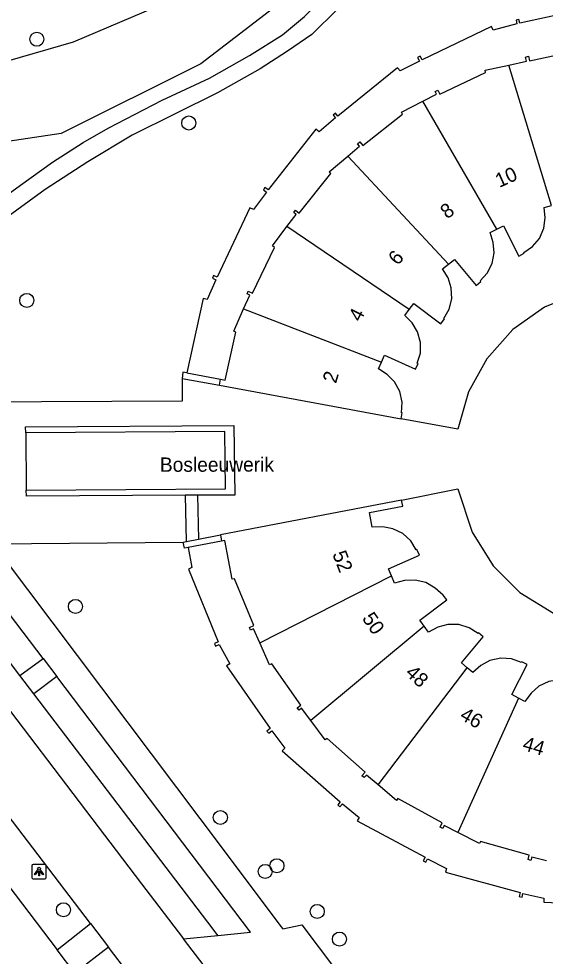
# Model space of a CAD drawing. Extents: x 156664 to 157568, y 383571 to 384421.
# Drawn here: x 157008.2 to 157044.9, y 384065.3 to 384130.7 of the extents above; entities that cross this region are included whole.
import ezdxf

# ---------------------------------------------------------------- set-up
doc = ezdxf.new("R2010")
doc.units = 0
for name, color, linetype in [('IMGEO_Boom', 7, 'Continuous'), ('IMGEO_Fietspad_gesloten', 7, 'Continuous'), ('IMGEO_Greppel_droge_sloot', 7, 'Continuous'), ('IMGEO_Groenvoorziening', 7, 'Continuous'), ('IMGEO_Lichtpunt', 7, 'Continuous'), ('IMGEO_Muur', 7, 'Continuous'), ('IMGEO_Openbare_ruimte_label', 7, 'Continuous'), ('IMGEO_Pand', 7, 'Continuous'), ('IMGEO_Pand_nummerreeks', 7, 'Continuous'), ('IMGEO_Parkeervlak_open', 7, 'Continuous'), ('IMGEO_Rijbaan_lokaal_gesloten', 7, 'Continuous'), ('IMGEO_Rijbaan_lokaal_open', 7, 'Continuous'), ('IMGEO_Voetpad_gesloten', 7, 'Continuous'), ('IMGEO_Voetpad_halfverhard', 7, 'Continuous'), ('IMGEO_Voetpad_open', 7, 'Continuous')]:
    doc.layers.add(name, color=color, linetype=linetype)

msp = doc.modelspace()

# ---------------------------------------------------------------- linework, layer by layer
at = {"layer": 'IMGEO_Boom'}
for centre in [(157009.428, 384129.265), (157020.016, 384123.422), (157008.728, 384111.051), (157012.118, 384089.707), (157022.219, 384074.989), (157026.16, 384071.625), (157025.342, 384071.225), (157011.285, 384068.552), (157028.973, 384068.439), (157030.517, 384066.51)]:
    msp.add_circle(centre, 0.489, dxfattribs=at)
at = {"layer": 'IMGEO_Fietspad_gesloten'}
for points in [[(156992.949, 384089.063), (156993.81, 384088.011), (156999.63, 384080.515), (157010.848, 384065.748)], [(157012.072, 384064.137), (157010.848, 384065.748)]]:
    msp.add_lwpolyline(points, dxfattribs=at)
at = {"layer": 'IMGEO_Greppel_droge_sloot'}
msp.add_lwpolyline([(157029.595, 384139.138), (157030.878, 384136.293), (157028.032, 384133.073), (157020.852, 384127.544), (157011.124, 384122.683), (157001.811, 384121.29), (156998.763, 384122.638), (157003.697, 384126.69), (157011.975, 384129.074), (157020.136, 384132.567), (157029.595, 384139.138)], dxfattribs=at)
at = {"layer": 'IMGEO_Groenvoorziening'}
for points in [[(157048.127, 384131.481), (157043.095, 384130.384), (157043.028, 384130.645), (157042.825, 384130.593), (157042.892, 384130.331), (157041.237, 384129.908), (157041.118, 384130.156), (157036.279, 384127.836), (157036.154, 384128.079), (157035.969, 384127.983), (157036.093, 384127.743), (157034.746, 384127.057), (157034.572, 384127.271), (157030.415, 384123.905), (157030.234, 384124.118), (157030.072, 384123.98), (157030.247, 384123.775), (157029.094, 384122.813), (157028.877, 384122.984), (157025.551, 384118.755), (157025.324, 384118.924), (157025.217, 384118.753), (157025.434, 384118.592), (157024.534, 384117.386), (157024.285, 384117.503), (157022.003, 384112.671), (157021.75, 384112.785), (157021.666, 384112.595), (157021.913, 384112.485), (157021.294, 384111.118), (157021.03, 384111.176), (157019.882, 384105.99)], [(157019.977, 384093.821), (157020.243, 384092.419), (157019.993, 384092.314), (157022.059, 384087.243), (157021.801, 384087.126), (157021.887, 384086.945), (157022.134, 384087.057), (157022.88, 384085.711), (157022.658, 384085.557), (157025.688, 384081.187), (157025.465, 384081.017), (157025.587, 384080.858), (157025.802, 384081.021), (157026.715, 384079.829), (157026.537, 384079.627), (157030.572, 384076.083), (157030.398, 384075.874), (157030.555, 384075.734), (157030.727, 384075.942), (157031.892, 384074.991), (157031.764, 384074.753), (157036.482, 384072.223), (157036.352, 384071.966), (157036.528, 384071.869), (157036.65, 384072.11), (157037.988, 384071.44), (157037.913, 384071.18), (157043.117, 384069.755), (157043.052, 384069.484), (157043.241, 384069.428), (157043.304, 384069.69), (157044.771, 384069.367), (157044.759, 384069.094), (157050.113, 384068.857)]]:
    msp.add_lwpolyline(points, dxfattribs=at)
at = {"layer": 'IMGEO_Lichtpunt'}
for p, q in [((157009.085, 384071.62), (157009.085, 384070.813)), ((157009.085, 384071.62), (157009.085, 384070.813)), ((157009.987, 384071.715), (157009.179, 384071.715)), ((157009.987, 384071.715), (157009.179, 384071.715)), ((157010.081, 384070.813), (157010.081, 384071.62)), ((157010.081, 384070.813), (157010.081, 384071.62)), ((157009.179, 384070.719), (157009.987, 384070.719)), ((157009.179, 384070.719), (157009.987, 384070.719))]:
    msp.add_line(p, q, dxfattribs=at)
for points in [[(157009.459, 384071.284), (157009.498, 384071.256), (157009.31, 384070.994), (157009.272, 384071.021), (157009.459, 384071.284)], [(157009.561, 384071.236), (157009.608, 384071.236), (157009.608, 384070.914), (157009.561, 384070.914), (157009.561, 384071.236)], [(157009.671, 384071.256), (157009.709, 384071.283), (157009.896, 384071.021), (157009.857, 384070.993), (157009.671, 384071.256)]]:
    msp.add_lwpolyline(points, dxfattribs=at)
msp.add_circle((157009.584, 384071.418), 0.0994, dxfattribs=at)
for centre, start, end in [((157009.179, 384071.62), 90, 180), ((157009.179, 384071.62), 90, 180), ((157009.987, 384071.62), 0, 90), ((157009.987, 384071.62), 0, 90), ((157009.179, 384070.813), 180, 270), ((157009.179, 384070.813), 180, 270), ((157009.987, 384070.813), 270, 0), ((157009.987, 384070.813), 270, 360)]:
    msp.add_arc(centre, 0.0946, start, end, dxfattribs=at)
at = {"layer": 'IMGEO_Muur'}
for points in [[(157019.882, 384105.99), (157019.616, 384106.039), (157019.547, 384105.61)], [(157019.882, 384105.99), (157022.239, 384105.555)], [(157019.547, 384105.61), (157022.161, 384105.134)], [(157008.652, 384101.811), (157008.649, 384102.241), (157023.17, 384102.337), (157023.227, 384097.478), (157020.634, 384097.464)], [(157008.697, 384097.827), (157022.572, 384097.905), (157022.525, 384101.903), (157008.652, 384101.811)], [(157019.801, 384097.459), (157008.7, 384097.397), (157008.697, 384097.827)], [(157020.634, 384097.464), (157019.801, 384097.459)], [(157019.622, 384094.19), (157019.862, 384094.236)], [(157019.977, 384093.821), (157019.712, 384093.771), (157019.622, 384094.19)], [(157019.862, 384094.236), (157020.693, 384094.396)], [(157022.3, 384094.267), (157019.977, 384093.821)], [(157020.693, 384094.396), (157022.222, 384094.691)]]:
    msp.add_lwpolyline(points, dxfattribs=at)
at = {"layer": 'IMGEO_Pand'}
for points in [[(157042.322, 384127.458), (157043.551, 384127.728), (157043.486, 384128.025), (157043.689, 384128.077), (157043.759, 384127.755), (157047.016, 384128.46), (157047.013, 384128.62), (157048.696, 384128.653)], [(157036.336, 384124.956), (157037.285, 384125.441), (157037.192, 384125.629), (157037.375, 384125.722), (157037.52, 384125.433), (157040.705, 384126.94), (157040.67, 384127.096), (157042.322, 384127.458)], [(157045.3, 384117.659), (157042.322, 384127.458)], [(157031.102, 384121.115), (157031.914, 384121.8), (157031.788, 384121.968), (157031.944, 384122.1), (157032.139, 384121.853), (157034.906, 384124.041), (157034.832, 384124.186), (157036.336, 384124.956)], [(157041.479, 384116.024), (157036.336, 384124.956)], [(157026.859, 384116.199), (157027.498, 384117.048), (157027.336, 384117.178), (157027.45, 384117.345), (157027.713, 384117.136), (157029.919, 384119.902), (157029.814, 384120.027), (157031.102, 384121.115)], [(157031.102, 384121.115), (157038.119, 384113.575)], [(157041.479, 384116.024), (157041.945, 384116.251), (157043.012, 384114.146), (157043.389, 384114.342), (157043.361, 384114.395), (157043.97, 384114.805), (157044.455, 384115.378), (157044.755, 384116.087), (157044.858, 384116.808), (157044.788, 384117.54), (157045.3, 384117.659)], [(157023.841, 384110.452), (157024.273, 384111.42), (157024.086, 384111.515), (157024.163, 384111.705), (157024.455, 384111.565), (157025.984, 384114.749), (157025.846, 384114.853), (157026.859, 384116.199)], [(157035.386, 384110.419), (157026.859, 384116.199)], [(157038.119, 384113.575), (157038.527, 384113.904), (157040.038, 384112.093), (157040.361, 384112.367), (157040.322, 384112.413), (157040.824, 384112.949), (157041.169, 384113.615), (157041.304, 384114.373), (157041.243, 384115.099), (157041.012, 384115.797), (157041.479, 384116.024)], [(157035.386, 384110.419), (157035.706, 384110.832), (157037.593, 384109.417), (157037.847, 384109.757), (157037.799, 384109.793), (157038.167, 384110.428), (157038.354, 384111.155), (157038.316, 384111.924), (157038.094, 384112.618), (157037.712, 384113.246), (157038.119, 384113.575)], [(157022.239, 384105.555), (157022.552, 384105.497), (157023.303, 384108.845), (157023.154, 384108.912), (157023.841, 384110.452)], [(157023.841, 384110.452), (157033.449, 384106.75)], [(157033.449, 384106.75), (157033.667, 384107.221), (157035.824, 384106.264), (157035.999, 384106.642), (157035.944, 384106.666), (157036.157, 384107.369), (157036.172, 384108.119), (157035.958, 384108.858), (157035.581, 384109.483), (157035.065, 384110.006), (157035.386, 384110.419)], [(157034.816, 384102.793), (157034.893, 384103.21), (157034.834, 384103.221), (157034.884, 384103.953), (157034.731, 384104.688), (157034.357, 384105.36), (157033.85, 384105.885), (157033.23, 384106.279), (157033.449, 384106.75)], [(157022.161, 384105.134), (157022.239, 384105.555)], [(157022.161, 384105.134), (157034.816, 384102.793)], [(157034.843, 384097.129), (157022.222, 384094.691)], [(157034.144, 384091.831), (157033.933, 384092.33), (157036.091, 384093.284), (157035.916, 384093.67), (157035.862, 384093.645), (157035.484, 384094.275), (157034.939, 384094.79), (157034.248, 384095.129), (157033.532, 384095.27), (157032.798, 384095.24), (157032.618, 384096.262), (157034.935, 384096.708), (157034.843, 384097.129)], [(157022.222, 384094.691), (157022.3, 384094.267)], [(157024.965, 384087.165), (157024.524, 384088.144), (157024.329, 384088.057), (157024.248, 384088.24), (157024.55, 384088.375), (157023.209, 384091.632), (157023.046, 384091.608), (157022.52, 384094.309), (157022.3, 384094.267)], [(157024.965, 384087.165), (157034.144, 384091.831)], [(157036.419, 384088.326), (157036.114, 384088.747), (157038.002, 384090.163), (157037.745, 384090.5), (157037.189, 384090.993), (157036.541, 384091.373), (157035.792, 384091.548), (157035.063, 384091.526), (157034.354, 384091.332), (157034.144, 384091.831)], [(157036.419, 384088.326), (157028.525, 384081.743)], [(157039.423, 384085.436), (157039.03, 384085.776), (157040.545, 384087.586), (157040.214, 384087.86), (157040.176, 384087.814), (157039.561, 384088.215), (157038.845, 384088.44), (157038.075, 384088.441), (157037.37, 384088.255), (157036.723, 384087.906), (157036.419, 384088.326)], [(157028.525, 384081.743), (157027.879, 384082.603), (157027.702, 384082.469), (157027.58, 384082.628), (157027.827, 384082.821), (157025.796, 384085.699), (157025.654, 384085.635), (157024.965, 384087.165)], [(157042.986, 384083.317), (157042.528, 384083.561), (157043.604, 384085.661), (157043.224, 384085.85), (157043.198, 384085.797), (157042.507, 384086.047), (157041.759, 384086.101), (157041.009, 384085.927), (157040.366, 384085.584), (157039.816, 384085.097), (157039.423, 384085.436)], [(157033.207, 384077.256), (157039.423, 384085.436)], [(157046.949, 384082.039), (157046.447, 384082.173), (157047.019, 384084.461), (157046.602, 384084.562), (157046.588, 384084.504), (157045.859, 384084.595), (157045.117, 384084.482), (157044.425, 384084.146), (157043.873, 384083.67), (157043.444, 384083.073), (157042.986, 384083.317)], [(157042.986, 384083.317), (157038.778, 384073.936)], [(157033.207, 384077.256), (157032.397, 384077.939), (157032.244, 384077.766), (157032.086, 384077.905), (157032.308, 384078.156), (157029.656, 384080.496), (157029.531, 384080.402), (157028.525, 384081.743)], [(157038.778, 384073.936), (157037.82, 384074.428), (157037.718, 384074.23), (157037.54, 384074.324), (157037.686, 384074.624), (157034.593, 384076.31), (157034.484, 384076.18), (157033.207, 384077.256)], [(157044.955, 384071.963), (157043.919, 384072.224), (157043.861, 384071.996), (157043.665, 384072.048), (157043.741, 384072.369), (157040.356, 384073.306), (157040.283, 384073.163), (157038.778, 384073.936)]]:
    msp.add_lwpolyline(points, dxfattribs=at)
at = {"layer": 'IMGEO_Parkeervlak_open'}
for points in [[(157008.252, 384084.883), (157004.436, 384089.91), (157002.783, 384088.679)], [(157022.05, 384066.767), (157021.725, 384067.195), (157009.23, 384083.609)]]:
    msp.add_lwpolyline(points, dxfattribs=at)
at = {"layer": 'IMGEO_Rijbaan_lokaal_gesloten'}
msp.add_lwpolyline([(157008.652, 384101.811), (157008.697, 384097.827)], dxfattribs=at)
at = {"layer": 'IMGEO_Rijbaan_lokaal_open'}
for points in [[(157013.176, 384067.588), (156995.355, 384090.962)], [(157002.783, 384088.679), (157016.726, 384070.36), (157017.934, 384068.772), (157019.642, 384066.527)], [(157013.176, 384067.588), (157014.424, 384065.95)], [(157021.082, 384064.634), (157019.642, 384066.527)], [(157067.449, 383996.186), (157062.167, 384003.14), (157022.83, 384054.925), (157020.102, 384058.503), (157014.424, 384065.95)]]:
    msp.add_lwpolyline(points, dxfattribs=at)
at = {"layer": 'IMGEO_Voetpad_gesloten'}
for points in [[(157019.862, 384094.236), (157019.801, 384097.459)], [(157020.634, 384097.464), (157020.693, 384094.396)]]:
    msp.add_lwpolyline(points, dxfattribs=at)
at = {"layer": 'IMGEO_Voetpad_halfverhard'}
for points in [[(156994.084, 384110.528), (156997.761, 384111.981), (157001.193, 384113.9), (157008.294, 384119.078), (157010.532, 384120.698), (157012.649, 384122.072), (157014.412, 384123.063), (157018.159, 384125.008), (157021.465, 384126.549), (157024.262, 384128.135), (157026.54, 384129.566), (157028.082, 384130.851), (157029.891, 384132.736), (157030.956, 384134.504), (157031.273, 384135.669), (157031.39, 384136.396), (157031.332, 384137.044), (157031.044, 384137.849), (157029.957, 384139.919)], [(157032.41, 384137.9), (157032.57, 384136.354), (157032.501, 384134.853), (157032.044, 384133.57), (157030.382, 384131.364), (157028.584, 384129.591), (157026.896, 384128.424), (157025.001, 384127.192), (157022.013, 384125.527), (157019.077, 384124.071), (157016.072, 384122.571), (157012.993, 384120.722), (157010.012, 384118.789), (157006.916, 384116.533), (157004.398, 384114.6), (157001.439, 384112.453), (156999.469, 384111.238), (156995.242, 384109.027)]]:
    msp.add_lwpolyline(points, dxfattribs=at)
at = {"layer": 'IMGEO_Voetpad_open'}
for points in [[(157047.332, 384111.598), (157044.809, 384110.57), (157042.603, 384109.015), (157040.782, 384106.976), (157039.52, 384104.666), (157038.761, 384102.061), (157034.816, 384102.793)], [(157019.547, 384105.61), (157019.552, 384104.012), (157004.825, 384103.959), (157000.672, 384101.738)], [(157034.843, 384097.129), (157038.769, 384097.919), (157039.761, 384094.89), (157041.241, 384092.533), (157043.089, 384090.685), (157045.436, 384089.228)], [(157009.86, 384086.08), (157005.587, 384091.67), (157002.48, 384095.843)], [(157006.39, 384094.063), (157019.622, 384094.19)], [(157006.39, 384094.063), (157007.009, 384093.232), (157019.16, 384077.074), (157022.404, 384072.759), (157026.442, 384067.389), (157026.562, 384067.229), (157027.349, 384067.389), (157027.895, 384067.5), (157043.532, 384046.733)], [(157008.252, 384084.883), (157009.86, 384086.08)], [(157009.86, 384086.08), (157010.828, 384084.813)], [(157009.23, 384083.609), (157008.252, 384084.883)], [(157010.828, 384084.813), (157009.23, 384083.609)], [(157022.05, 384066.767), (157024.311, 384066.986), (157010.828, 384084.813)], [(157010.848, 384065.748), (157013.176, 384067.588)], [(157019.642, 384066.527), (157022.05, 384066.767)], [(157014.424, 384065.95), (157012.072, 384064.137)]]:
    msp.add_lwpolyline(points, dxfattribs=at)

# ---------------------------------------------------------------- texts
at = {"layer": 'IMGEO_Openbare_ruimte_label'}
msp.add_text('Bosleeuwerik', height=1, rotation=0.11459, dxfattribs=at).set_placement((157018.006, 384099.095))
at = {"layer": 'IMGEO_Pand_nummerreeks'}
for s, rotation, p in [('10', 24.39122, (157041.662, 384118.89)), ('8', 37.30111, (157038.029, 384116.692)), ('6', 50.27122, (157034.597, 384113.441)), ('4', 63.33611, (157031.992, 384109.502)), ('2', 73.18478, (157030.276, 384105.214)), ('52', 291.30255, (157030.008, 384093.366)), ('50', 304.23789, (157032.061, 384088.872)), ('48', 317.27834, (157035.049, 384084.988)), ('46', 330.48326, (157038.839, 384081.88)), ('44', 343.31032, (157043.215, 384079.717))]:
    msp.add_text(s, height=1, rotation=rotation, dxfattribs=at).set_placement(p)

doc.saveas('drawing.dxf')
